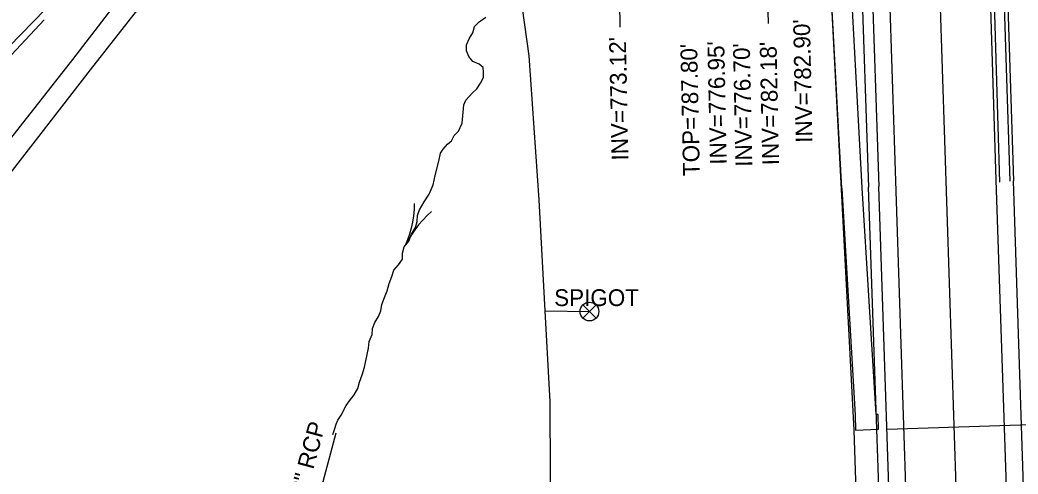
# Model space of a CAD drawing. Extents: x 1627482 to 1629573, y 760826 to 766301.
# Drawn here: x 1628256.5 to 1628494.4, y 761404.2 to 761512.3 of the extents above; entities that cross this region are included whole.
import ezdxf

# ---------------------------------------------------------------- set-up
doc = ezdxf.new("R2010")
doc.units = 0
for name, color, linetype in [('Exist Guardrail', 7, 'Continuous'), ('Exist Hydro Stream Flow Arrow CELL', 7, 'Continuous'), ('Exist Hydro Stream or Body of Water', 7, 'Continuous'), ('Exist Roads Change in Surface', 7, 'Continuous'), ('Exist Roads Curbs', 7, 'Continuous'), ('Exist Roads EOP', 7, 'Continuous'), ('Exist Roads EOP Other', 7, 'Continuous'), ('Exist Roads EOT', 7, 'Continuous'), ('Exist Structure Minor Catch Basin Top Elevation', 7, 'Continuous'), ('Exist Structure Minor Pipes CMP 18 Inch Invert', 7, 'Continuous'), ('Exist Structure Minor Pipes CMP 18 Inch Leader', 7, 'Continuous'), ('Exist Structure Minor Pipes RCP 18 Inch', 7, 'Continuous'), ('Exist Structure Minor Pipes RCP 18 Inch Invert', 7, 'Continuous'), ('Exist Structure Minor Pipes RCP 18 Inch Text', 7, 'Continuous'), ('Exist Utilities Gas UG Line SUE', 7, 'Continuous'), ('Exist Utilities Sanitary Sewer UG Line', 7, 'Continuous'), ('Exist Utilities Water UG Line SUE', 7, 'Continuous'), ('Exist Utilities Water Valve CELL', 7, 'Continuous'), ('Exist Utilities Water Valve Text', 7, 'Continuous')]:
    doc.layers.add(name, color=color, linetype=linetype)

# ---------------------------------------------------------------- blocks, each defined once
blk = doc.blocks.new('EXIST UTILITIES WATER VALVE')
at = {"layer": 'Exist Utilities Water Valve CELL'}
blk.add_lwpolyline([(0.0315, 0.0315), (-0.0315, -0.0315), (0, 0), (0.0315, -0.0315), (-0.0315, 0.0315)], dxfattribs=at)
blk.add_circle((0, 0), 0.0445, dxfattribs=at)

msp = doc.modelspace()

# ---------------------------------------------------------------- linework, layer by layer
at = {"layer": 'Exist Guardrail'}
msp.add_lwpolyline([(1628456.07, 761390.66), (1628455.29, 761414.65), (1628447.02, 761571.58)], dxfattribs=at)
at = {"layer": 'Exist Hydro Stream Flow Arrow CELL'}
msp.add_line((1628350.44, 761463.11), (1628350.44, 761463.11), dxfattribs=at)
for points in [[(1628350.46, 761468.61), (1628350.44, 761467.15), (1628350.26, 761465.66), (1628350.07, 761464.19), (1628349.76, 761462.78), (1628349.36, 761461.35), (1628348.88, 761459.94), (1628348.33, 761458.58)], [(1628354.61, 761466.69), (1628353.51, 761465.73), (1628352.49, 761464.63), (1628351.5, 761463.53), (1628350.62, 761462.38), (1628349.79, 761461.15), (1628349.02, 761459.87), (1628348.33, 761458.58)]]:
    msp.add_lwpolyline(points, dxfattribs=at)
at = {"layer": 'Exist Hydro Stream or Body of Water'}
msp.add_lwpolyline([(1628331.05, 761413.59), (1628331.53, 761415.01), (1628331.87, 761416.05), (1628332.29, 761417), (1628333.08, 761418.25), (1628334.22, 761420.49), (1628335, 761421.63), (1628336.14, 761423.08), (1628337.02, 761424.59), (1628337.45, 761426.05), (1628338.05, 761427.85), (1628338.6, 761429.62), (1628338.93, 761431.19), (1628339.28, 761432.66), (1628339.6, 761434.13), (1628339.75, 761435.74), (1628340.44, 761437.46), (1628340.52, 761438.84), (1628341.1, 761440.27), (1628341.95, 761441.73), (1628342.48, 761443.04), (1628342.77, 761444.59), (1628343.36, 761446.21), (1628344.03, 761447.81), (1628344.49, 761449.56), (1628345.14, 761451.27), (1628345.64, 761452.73), (1628346.69, 761454.04), (1628347.69, 761455.39), (1628347.7, 761456.81), (1628348.1, 761458.28), (1628349.16, 761459.67), (1628349.85, 761461.28), (1628350.73, 761462.9), (1628351.15, 761464.32), (1628351.26, 761465.73), (1628351.73, 761467.14), (1628352.83, 761469.02), (1628353.99, 761470.81), (1628355.01, 761473.07), (1628355.44, 761475.32), (1628356.3, 761478.71), (1628356.72, 761480.62), (1628357.32, 761481.55), (1628358.41, 761482.78), (1628359.37, 761483.52), (1628359.96, 761484.79), (1628361.05, 761485.84), (1628361.89, 761487.73), (1628362.27, 761492.12), (1628362.75, 761493.21), (1628364.38, 761494.98), (1628365.37, 761495.91), (1628366.23, 761497.26), (1628366.98, 761498.63), (1628366.95, 761499.92), (1628366.89, 761501.04), (1628365.93, 761501.79), (1628364.45, 761502.46), (1628363.49, 761503.62), (1628362.93, 761504.96), (1628362.89, 761506.43), (1628363.67, 761508), (1628364.44, 761509.26), (1628364.84, 761510.78), (1628365.97, 761511.89), (1628367.5, 761513)], dxfattribs=at)
at = {"layer": 'Exist Roads Change in Surface'}
msp.add_line((1628463.13, 761414.9), (1628546.09, 761417.62), dxfattribs=at)
at = {"layer": 'Exist Roads Curbs'}
for p, q in [((1628494.89, 761300.41), (1628489.17, 761474.17)), ((1628498.88, 761300.78), (1628493.3, 761474.03)), ((1628467.68, 761214.72), (1628458.72, 761472.48))]:
    msp.add_line(p, q, dxfattribs=at)
msp.add_lwpolyline([(1628455.39, 761572.6), (1628456.93, 761526.55), (1628458.72, 761472.48)], dxfattribs=at)
at = {"layer": 'Exist Roads EOP'}
msp.add_line((1628469.68, 761214.54), (1628461.19, 761472.7), dxfattribs=at)
for points in [[(1628489.17, 761474.17), (1628487.46, 761528.11), (1628485.83, 761577.65), (1628485.02, 761600.55)], [(1628489.16, 761600.58), (1628489.9, 761577.28), (1628491.56, 761528), (1628491.52, 761527.93), (1628493.3, 761474.03)], [(1628457.85, 761575.83), (1628459.36, 761526.69), (1628461.19, 761472.7)]]:
    msp.add_lwpolyline(points, dxfattribs=at)
at = {"layer": 'Exist Roads EOP Other'}
for p, q in [((1628460.52, 761418.35), (1628457.17, 761472.32)), ((1628455.52, 761418.19), (1628455.63, 761414.66)), ((1628461.13, 761414.84), (1628461.02, 761418.37)), ((1628455.63, 761414.66), (1628461.13, 761414.84))]:
    msp.add_line(p, q, dxfattribs=at)
for points in [[(1628485.78, 761600.37), (1628486.61, 761575.78), (1628488.32, 761527.13), (1628489.96, 761473.71)], [(1628492.48, 761473.91), (1628490.73, 761528.03), (1628489.23, 761577.07), (1628488.95, 761583.4), (1628486.41, 761592.76), (1628486.05, 761597.47), (1628488.47, 761597.61), (1628488.47, 761597.62), (1628488.4, 761600.55)], [(1628452.34, 761472.22), (1628449.76, 761520.48), (1628447.21, 761570.01)], [(1628457.17, 761472.32), (1628454.62, 761520.72), (1628452.05, 761570.39)], [(1628452.34, 761472.22), (1628455.52, 761418.19)], [(1628461.02, 761418.37), (1628460.52, 761418.35)]]:
    msp.add_lwpolyline(points, dxfattribs=at)
at = {"layer": 'Exist Roads EOT'}
for p, q in [((1628473.68, 761214.67), (1628455.37, 761774.37)), ((1628486.98, 761175.08), (1628473.29, 761593.87))]:
    msp.add_line(p, q, dxfattribs=at)
at = {"layer": 'Exist Structure Minor Pipes CMP 18 Inch Leader'}
msp.add_lwpolyline([(1628420.32, 761546.24), (1628399.35, 761516.59), (1628399.47, 761510.6)], dxfattribs=at)
at = {"layer": 'Exist Structure Minor Pipes RCP 18 Inch'}
for p, q in [((1628262.27, 761512.32), (1628202.65, 761449.06)), ((1628331.78, 761413.92), (1628323.59, 761383.59))]:
    msp.add_line(p, q, dxfattribs=at)
at = {"layer": 'Exist Structure Minor Pipes RCP 18 Inch Invert'}
msp.add_lwpolyline([(1628457.69, 761575.26), (1628434.66, 761517.49), (1628434.78, 761511.49)], dxfattribs=at)
at = {"layer": 'Exist Utilities Gas UG Line SUE'}
for points in [[(1628107.21, 761398.96), (1628106.54, 761402.67), (1628116.88, 761405.77), (1628151.1, 761408.38), (1628180.43, 761414.9), (1628192.91, 761420.7), (1628204.95, 761428.91), (1628225.97, 761449.06), (1628243.25, 761470.03), (1628269.14, 761502.92), (1628294.62, 761536.12), (1628323.09, 761572.16), (1628354.96, 761616.04), (1628378.95, 761653.33), (1628389.59, 761672.5), (1628403.67, 761697.73), (1628413.63, 761729.38), (1628419.89, 761728.8)], [(1628074.03, 761404.42), (1628082.95, 761406.14), (1628117.81, 761411.15), (1628150.65, 761410.46), (1628162.9, 761405.76), (1628195.7, 761416.48), (1628218.76, 761434.91), (1628247.28, 761466.97), (1628273.32, 761500.41), (1628299.4, 761533.69), (1628331.06, 761576.43), (1628354.05, 761607.59), (1628380.38, 761646.98), (1628399.62, 761680.21), (1628418.94, 761719.68)]]:
    msp.add_lwpolyline(points, dxfattribs=at)
at = {"layer": 'Exist Utilities Sanitary Sewer UG Line'}
msp.add_line((1628387.66, 761643.18), (1628150.8, 761400.29), dxfattribs=at)
at = {"layer": 'Exist Utilities Water UG Line SUE'}
for points in [[(1628390.25, 761359.33), (1628383, 761386.83), (1628382.82, 761421.37), (1628381.67, 761443.04), (1628380.23, 761469.51), (1628377.88, 761503.76), (1628374.09, 761530.56)], [(1628381.67, 761443.04), (1628392.22, 761442.89)]]:
    msp.add_lwpolyline(points, dxfattribs=at)

# ---------------------------------------------------------------- block references
at = {"layer": 'Exist Utilities Water Valve CELL', "xscale": 50, "yscale": 50}
msp.add_blockref('EXIST UTILITIES WATER VALVE', (1628392.22, 761442.89), dxfattribs=at)

# ---------------------------------------------------------------- texts
at = {"layer": 'Exist Structure Minor Catch Basin Top Elevation'}
msp.add_text("TOP=787.80'", height=4, rotation=91.2053, dxfattribs=at).set_placement((1628418.54, 761475.19))
at = {"layer": 'Exist Structure Minor Pipes CMP 18 Inch Invert'}
for s, p in [("INV=773.12'", (1628401.51, 761478.9)), ("INV=776.70'", (1628431.04, 761477.41))]:
    msp.add_text(s, height=4, rotation=91.2053, dxfattribs=at).set_placement(p)
at = {"layer": 'Exist Structure Minor Pipes RCP 18 Inch Invert'}
for s, p in [("INV=782.90'", (1628445.37, 761483.11)), ("INV=776.95'", (1628424.95, 761477.9)), ("INV=782.18'", (1628437.41, 761477.76))]:
    msp.add_text(s, height=4, rotation=91.2053, dxfattribs=at).set_placement(p)
at = {"layer": 'Exist Structure Minor Pipes RCP 18 Inch Text'}
msp.add_text('18" RCP', height=4, rotation=74.8973, dxfattribs=at).set_placement((1628323.97, 761396.12))
at = {"layer": 'Exist Utilities Water Valve Text'}
msp.add_text('SPIGOT', height=4, dxfattribs=at).set_placement((1628383.81, 761444.19))

doc.saveas('drawing.dxf')
